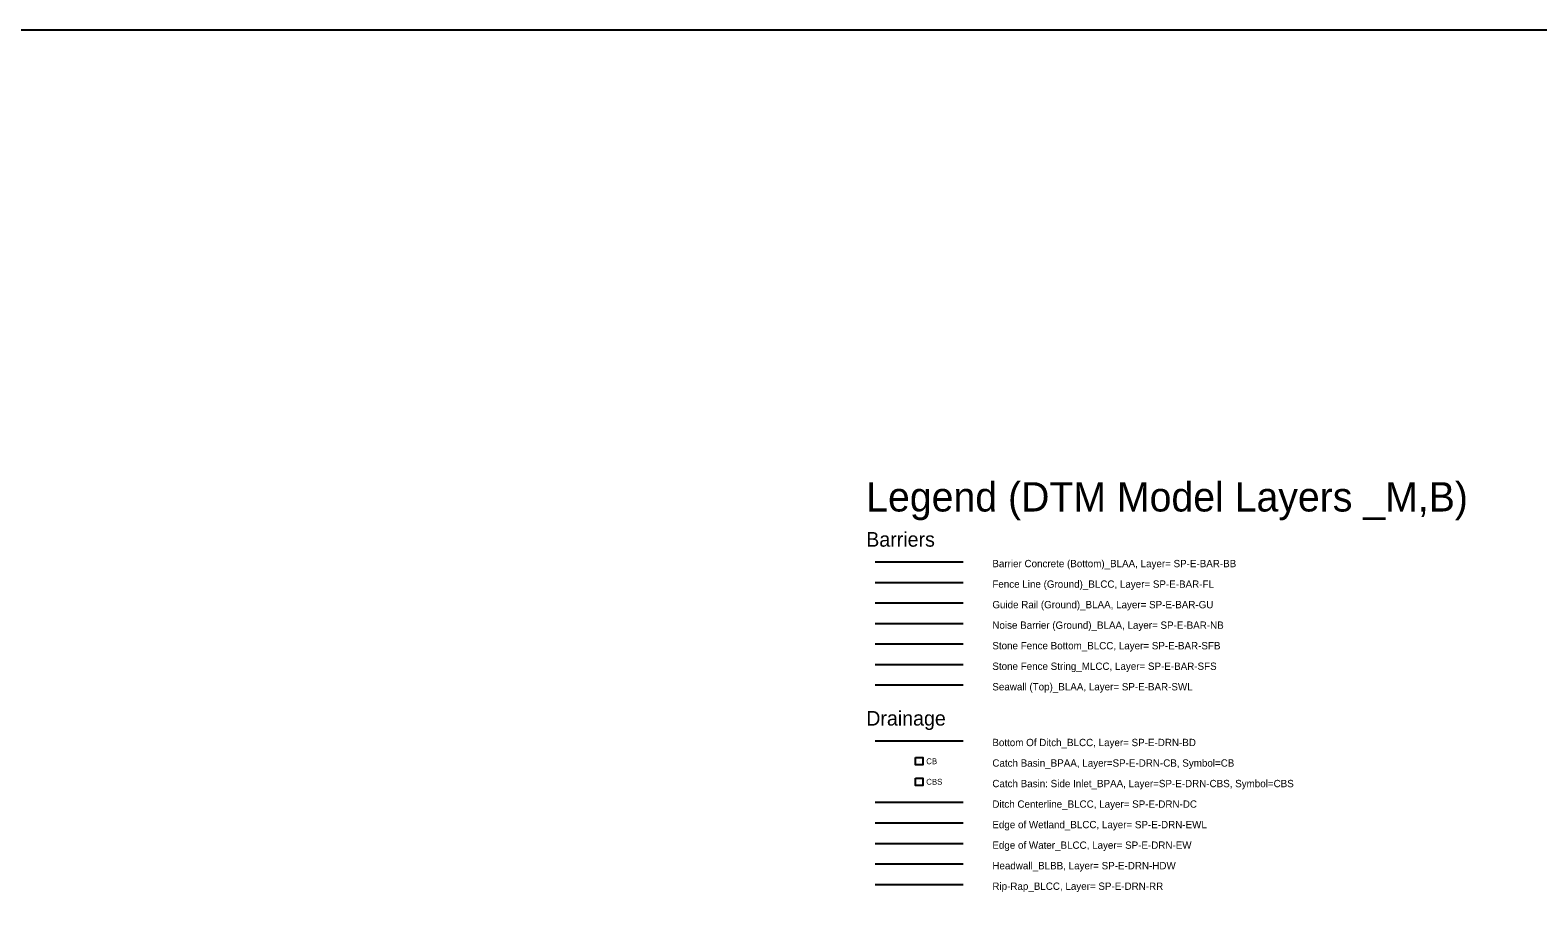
# Model space of a CAD drawing. Extents: x 500528 to 502626, y 4210261 to 4212624.
# Drawn here: x 501599 to 502113, y 4212327 to 4212624 of the extents above; entities that cross this region are included whole.
import ezdxf

# ---------------------------------------------------------------- set-up
doc = ezdxf.new("R2010")
doc.units = 0
for name, color, linetype in [('Default', 7, 'Continuous'), ('SP-E-BAR-BB', 7, 'Continuous'), ('SP-E-BAR-FL', 7, 'Continuous'), ('SP-E-BAR-GU', 7, 'Continuous'), ('SP-E-BAR-NB', 7, 'Continuous'), ('SP-E-BAR-SFB', 7, 'Continuous'), ('SP-E-BAR-SFS', 7, 'Continuous'), ('SP-E-BAR-SWL', 7, 'Continuous'), ('SP-E-DRN-BD', 7, 'Continuous'), ('SP-E-DRN-CB', 7, 'Continuous'), ('SP-E-DRN-CBS', 7, 'Continuous'), ('SP-E-DRN-DC', 7, 'Continuous'), ('SP-E-DRN-EW', 7, 'Continuous'), ('SP-E-DRN-EWL', 7, 'Continuous'), ('SP-E-DRN-HDW', 7, 'Continuous'), ('SP-E-DRN-RR', 7, 'Continuous'), ('SP-E-DRN-T', 7, 'Continuous')]:
    doc.layers.add(name, color=color, linetype=linetype)

# ---------------------------------------------------------------- blocks, each defined once
blk = doc.blocks.new('POINT_DISPLAY')
at = {"layer": 'Default'}
blk.add_line((0, 0), (0, 0), dxfattribs=at)
blk = doc.blocks.new('CB')
at = {"layer": 'SP-E-DRN-T'}
blk.add_lwpolyline([(-0.125, 0.125), (0.125, 0.125), (0.125, -0.125), (-0.125, -0.125), (-0.125, 0.125)], dxfattribs=at)
at = {"layer": 'SP-E-DRN-CB'}
blk.add_blockref('POINT_DISPLAY', (0, 0), dxfattribs=at)
at = {"layer": 'SP-E-DRN-T'}
blk.add_text('CB', height=0.2, dxfattribs=at).set_placement((0.246, -0.1))
blk = doc.blocks.new('CBS')
at = {"layer": 'SP-E-DRN-T'}
blk.add_lwpolyline([(-0.125, 0.125), (0.125, 0.125), (0.125, -0.125), (-0.125, -0.125), (-0.125, 0.125)], dxfattribs=at)
at = {"layer": 'SP-E-DRN-CBS'}
blk.add_blockref('POINT_DISPLAY', (0, 0), dxfattribs=at)
at = {"layer": 'SP-E-DRN-T'}
blk.add_text('CBS', height=0.2, dxfattribs=at).set_placement((0.246, -0.1))

msp = doc.modelspace()

# ---------------------------------------------------------------- linework, layer by layer
at = {"layer": 'Default'}
msp.add_lwpolyline([(500528.35, 4212623.85), (500528.35, 4210260.5), (502626.48, 4210260.5), (502626.48, 4212623.85), (500528.35, 4212623.85)], dxfattribs=at)
msp.add_lwpolyline([(500528.35, 4210260.5), (502626.48, 4210260.5), (502626.48, 4212623.85), (500528.35, 4212623.85)], close=True, dxfattribs=at)
at = {"layer": 'SP-E-BAR-BB'}
msp.add_line((501886.55, 4212442.59), (501916.55, 4212442.59), dxfattribs=at)
at = {"layer": 'SP-E-BAR-FL'}
msp.add_line((501886.55, 4212435.59), (501916.55, 4212435.59), dxfattribs=at)
at = {"layer": 'SP-E-BAR-GU'}
msp.add_line((501886.55, 4212428.59), (501916.55, 4212428.59), dxfattribs=at)
at = {"layer": 'SP-E-BAR-NB'}
msp.add_line((501886.55, 4212421.59), (501916.55, 4212421.59), dxfattribs=at)
at = {"layer": 'SP-E-BAR-SFB'}
msp.add_line((501886.55, 4212414.59), (501916.55, 4212414.59), dxfattribs=at)
at = {"layer": 'SP-E-BAR-SFS'}
msp.add_line((501886.55, 4212407.59), (501916.55, 4212407.59), dxfattribs=at)
at = {"layer": 'SP-E-BAR-SWL'}
msp.add_line((501886.55, 4212400.59), (501916.55, 4212400.59), dxfattribs=at)
at = {"layer": 'SP-E-DRN-BD'}
msp.add_line((501886.55, 4212381.59), (501916.55, 4212381.59), dxfattribs=at)
at = {"layer": 'SP-E-DRN-DC'}
msp.add_line((501886.55, 4212360.59), (501916.55, 4212360.59), dxfattribs=at)
at = {"layer": 'SP-E-DRN-EW'}
msp.add_line((501886.55, 4212346.59), (501916.55, 4212346.59), dxfattribs=at)
at = {"layer": 'SP-E-DRN-EWL'}
msp.add_line((501886.55, 4212353.59), (501916.55, 4212353.59), dxfattribs=at)
at = {"layer": 'SP-E-DRN-HDW'}
msp.add_line((501886.55, 4212339.59), (501916.55, 4212339.59), dxfattribs=at)
at = {"layer": 'SP-E-DRN-RR'}
msp.add_line((501886.55, 4212332.59), (501916.55, 4212332.59), dxfattribs=at)

# ---------------------------------------------------------------- block references
at = {"layer": 'SP-E-DRN-CB', "xscale": 10, "yscale": 10}
msp.add_blockref('CB', (501901.55, 4212374.59), dxfattribs=at)
at = {"layer": 'SP-E-DRN-CBS', "xscale": 10, "yscale": 10}
msp.add_blockref('CBS', (501901.55, 4212367.59), dxfattribs=at)

# ---------------------------------------------------------------- texts
at = {"layer": 'Default'}
for s, height, p in [('Legend (DTM Model Layers _M,B) ', 10, (501883.55, 4212459.74)), ('Barriers ', 5, (501883.55, 4212447.74)), ('Drainage ', 5, (501883.55, 4212386.74))]:
    msp.add_text(s, height=height, dxfattribs=at).set_placement(p)
at = {"layer": 'SP-E-BAR-BB'}
msp.add_text('Barrier Concrete (Bottom)_BLAA, Layer= SP-E-BAR-BB ', height=2.5, dxfattribs=at).set_placement((501926.55, 4212440.74))
at = {"layer": 'SP-E-BAR-FL'}
msp.add_text('Fence Line (Ground)_BLCC, Layer= SP-E-BAR-FL ', height=2.5, dxfattribs=at).set_placement((501926.55, 4212433.74))
at = {"layer": 'SP-E-BAR-GU'}
msp.add_text('Guide Rail (Ground)_BLAA, Layer= SP-E-BAR-GU ', height=2.5, dxfattribs=at).set_placement((501926.55, 4212426.74))
at = {"layer": 'SP-E-BAR-NB'}
msp.add_text('Noise Barrier (Ground)_BLAA, Layer= SP-E-BAR-NB ', height=2.5, dxfattribs=at).set_placement((501926.55, 4212419.74))
at = {"layer": 'SP-E-BAR-SFB'}
msp.add_text('Stone Fence Bottom_BLCC, Layer= SP-E-BAR-SFB ', height=2.5, dxfattribs=at).set_placement((501926.55, 4212412.74))
at = {"layer": 'SP-E-BAR-SFS'}
msp.add_text('Stone Fence String_MLCC, Layer= SP-E-BAR-SFS ', height=2.5, dxfattribs=at).set_placement((501926.55, 4212405.74))
at = {"layer": 'SP-E-BAR-SWL'}
msp.add_text('Seawall (Top)_BLAA, Layer= SP-E-BAR-SWL ', height=2.5, dxfattribs=at).set_placement((501926.55, 4212398.74))
at = {"layer": 'SP-E-DRN-BD'}
msp.add_text('Bottom Of Ditch_BLCC, Layer= SP-E-DRN-BD ', height=2.5, dxfattribs=at).set_placement((501926.55, 4212379.74))
at = {"layer": 'SP-E-DRN-CB'}
msp.add_text('Catch Basin_BPAA, Layer=SP-E-DRN-CB, Symbol=CB ', height=2.5, dxfattribs=at).set_placement((501926.55, 4212372.74))
at = {"layer": 'SP-E-DRN-CBS'}
msp.add_text('Catch Basin: Side Inlet_BPAA, Layer=SP-E-DRN-CBS, Symbol=CBS ', height=2.5, dxfattribs=at).set_placement((501926.55, 4212365.74))
at = {"layer": 'SP-E-DRN-DC'}
msp.add_text('Ditch Centerline_BLCC, Layer= SP-E-DRN-DC ', height=2.5, dxfattribs=at).set_placement((501926.55, 4212358.74))
at = {"layer": 'SP-E-DRN-EW'}
msp.add_text('Edge of Water_BLCC, Layer= SP-E-DRN-EW ', height=2.5, dxfattribs=at).set_placement((501926.55, 4212344.74))
at = {"layer": 'SP-E-DRN-EWL'}
msp.add_text('Edge of Wetland_BLCC, Layer= SP-E-DRN-EWL ', height=2.5, dxfattribs=at).set_placement((501926.55, 4212351.74))
at = {"layer": 'SP-E-DRN-HDW'}
msp.add_text('Headwall_BLBB, Layer= SP-E-DRN-HDW ', height=2.5, dxfattribs=at).set_placement((501926.55, 4212337.74))
at = {"layer": 'SP-E-DRN-RR'}
msp.add_text('Rip-Rap_BLCC, Layer= SP-E-DRN-RR ', height=2.5, dxfattribs=at).set_placement((501926.55, 4212330.74))

doc.saveas('drawing.dxf')
